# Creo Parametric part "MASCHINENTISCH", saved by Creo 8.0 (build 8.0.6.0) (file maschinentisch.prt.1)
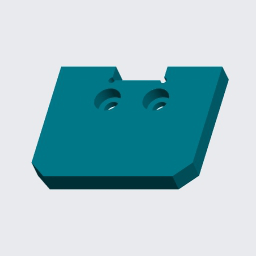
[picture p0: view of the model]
Units: millimeter Kilogram Sec (mmKs); MM, KILOGRAM, SECS
Materials in the file: STAHL

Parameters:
  SCHRAUBEN_GROESSE = "M4"
  METRISCH = "JA"
  WERKSTOFF = "Stahl"
  ERSTELLER = "ARINDA"
  BENENNUNG = "Maschinentisch"
  TEILETYP = "K"
  PTC_MASTER_MATERIAL = "STAHL"

Other parameters: ANSENKDURCHMESSER, ANSENKTIEFE, BOHR_DURCHM, MASSE

Created from: ARINDA_STARTTEIL.PRT

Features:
  1. coordinate system
  2. datum plane "RECHTS_Y-Z"
  3. datum plane "OBEN_X-Z"
  4. datum plane "VORNE_X-Y"
  5. datum axis
  6. datum axis
  7. datum axis
  8. datum point "PNT0"
  9. extrusion "Profil 1"
  10. extruded cut "Profil 2"
  11. extruded cut "Profil 3"
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
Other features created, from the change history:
  coordinate system "CS1"
  sketch "Skizze 1"
  hole "Bohrung 1"
  pattern "Muster 1"
  hole "Bohrung 1 [8]"
  chamfer "Fase 1"

Other named items: A_X, A_Y, A_Z, CS0

Layers: 01_ACHSEN, 01_ACHSEN_STD, 01_EBENEN_STD, 01_KOORDSYS_STD, 01_KURVEN, 01_PUNKTE_STD, VOLUMENGEOMETRIE

Notes: LÖSCHEN |  BOHREN (  | 4.500 | DURCH |   -(  |  ) BOHRUNG

Surfaces: 13 plane, 8 cylinder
